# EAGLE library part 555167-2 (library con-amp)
AMP connector
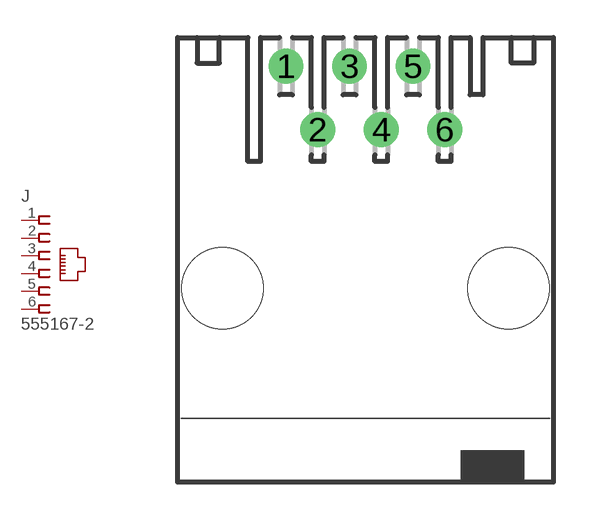
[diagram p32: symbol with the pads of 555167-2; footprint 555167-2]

Designator prefix J

## 555167-2 (OC_FARNELL: unknown; OC_NEWARK: unknown)  [555167-2]
1  1  pas
2  2  pas
3  3  pas
4  4  pas
5  5  pas
6  6  pas

## Footprint 555167-2 (pad centres in mm)
Modular Jack Keyed without Panel Stops
drill 0.889 round: 1 -3.175,7.747; 2 -1.905,5.207; 3 -0.635,7.747; 4 0.635,5.207; 5 1.905,7.747; 6 3.175,5.207
hole 3.251 at -5.715,-1.143
hole 3.251 at 5.715,-1.143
